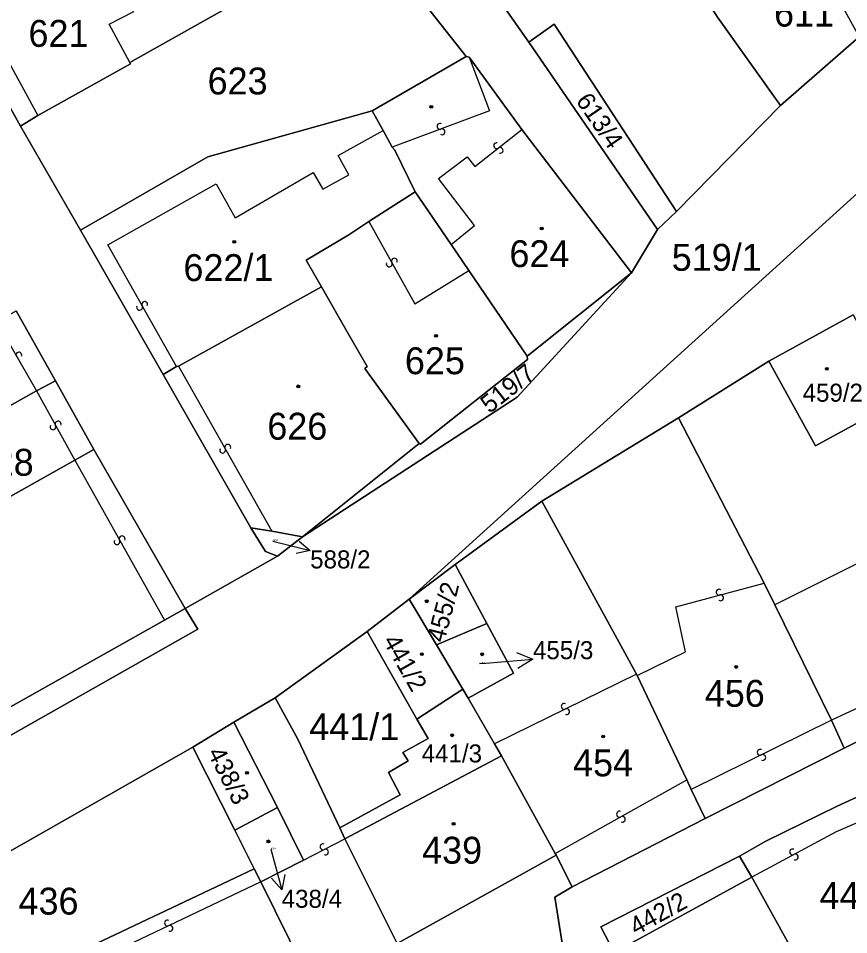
# Model space of a CAD drawing. Extents: x -598233 to -596890, y -1157848 to -1156431.
# Drawn here: x -597383.6 to -597331, y -1157497.1 to -1157439.2 of the extents above; entities that cross this region are included whole.
import ezdxf

# ---------------------------------------------------------------- set-up
doc = ezdxf.new("R2010")
doc.units = 0
for name, color, linetype in [('Level 1', 7, 'Continuous'), ('Level 13', 7, 'Continuous'), ('Level 3', 7, 'Continuous'), ('Level 4', 7, 'Continuous'), ('Level 5', 7, 'Continuous'), ('Level 57', 7, 'Continuous'), ('Level 60', 7, 'Continuous')]:
    doc.layers.add(name, color=color, linetype=linetype)

msp = doc.modelspace()

# ---------------------------------------------------------------- linework, layer by layer
at = {"layer": 'Level 1'}
for points in [[(-597376.5, -1157441.98), (-597366.03, -1157436.07), (-597362.03, -1157433.69), (-597361.89, -1157433.82), (-597361.56, -1157433.56)], [(-597361.56, -1157433.56), (-597355.23, -1157441.59)], [(-597354.11, -1157436.61), (-597351.28, -1157440.68)], [(-597388.35, -1157437.12), (-597383.41, -1157446)], [(-597339.34, -1157439.1), (-597335.35, -1157444.7)], [(-597351.28, -1157440.68), (-597349.67, -1157439.54), (-597341.93, -1157451.4)], [(-597335.35, -1157444.7), (-597330.38, -1157440.35)], [(-597351.28, -1157440.68), (-597343.14, -1157452.53)], [(-597361.17, -1157445.03), (-597355.23, -1157441.59)], [(-597355.23, -1157441.59), (-597355.05, -1157441.63)], [(-597355.05, -1157441.63), (-597351.71, -1157446.21)], [(-597382.33, -1157445.33), (-597376.47, -1157442.05), (-597376.5, -1157441.98)], [(-597379.63, -1157452.57), (-597371.58, -1157447.94), (-597361.17, -1157445.03)], [(-597361.17, -1157445.03), (-597360.49, -1157446.27)], [(-597341.93, -1157451.4), (-597335.35, -1157444.7)], [(-597383.41, -1157446), (-597382.33, -1157445.33)], [(-597383.41, -1157446), (-597379.63, -1157452.57)], [(-597360.49, -1157446.27), (-597359.91, -1157447.33)], [(-597344.79, -1157455.26), (-597351.71, -1157446.21)], [(-597358.47, -1157450.14), (-597359.74, -1157447.51), (-597359.91, -1157447.33)], [(-597358.85, -1157475.91), (-597329.82, -1157449.62)], [(-597361.39, -1157452.03), (-597358.47, -1157450.14)], [(-597356.19, -1157453.47), (-597358.47, -1157450.14)], [(-597341.93, -1157451.4), (-597343.14, -1157452.53)], [(-597364.38, -1157456.16), (-597365.35, -1157454.47), (-597362.66, -1157452.86), (-597361.39, -1157452.03)], [(-597379.63, -1157452.57), (-597374.4, -1157461.7)], [(-597343.14, -1157452.53), (-597344.79, -1157455.26)], [(-597355.07, -1157455.12), (-597356.19, -1157453.47)], [(-597344.79, -1157455.26), (-597352, -1157463.13), (-597365.58, -1157471.97)], [(-597351.38, -1157460.55), (-597355.07, -1157455.12)], [(-597344.79, -1157455.26), (-597351.38, -1157460.55)], [(-597373.42, -1157461.17), (-597364.38, -1157456.16)], [(-597364.38, -1157456.16), (-597362.67, -1157459.14), (-597361.49, -1157461.2), (-597361.64, -1157461.32), (-597358.21, -1157466.07)], [(-597381.21, -1157462.09), (-597383.69, -1157457.67)], [(-597330.77, -1157457.93), (-597336.09, -1157460.85)], [(-597358.21, -1157466.07), (-597358.13, -1157466.11), (-597351.35, -1157460.74), (-597351.38, -1157460.55)], [(-597374.4, -1157461.7), (-597373.56, -1157461.2)], [(-597373.56, -1157461.2), (-597373.42, -1157461.17)], [(-597336.09, -1157460.85), (-597341.81, -1157464.43)], [(-597336.09, -1157460.85), (-597333.15, -1157466.22), (-597327.85, -1157463.33)], [(-597374.4, -1157461.7), (-597368.86, -1157471.4)], [(-597381.21, -1157462.09), (-597382.41, -1157462.74)], [(-597378.79, -1157466.45), (-597381.21, -1157462.09)], [(-597390.52, -1157467.29), (-597382.41, -1157462.74)], [(-597341.81, -1157464.43), (-597350.45, -1157469.7)], [(-597341.81, -1157464.43), (-597336.4, -1157474.89)], [(-597379.99, -1157467.11), (-597378.79, -1157466.45)], [(-597378.79, -1157466.45), (-597373, -1157476.49)], [(-597365.58, -1157471.97), (-597358.21, -1157466.07)], [(-597388.09, -1157471.67), (-597379.99, -1157467.11)], [(-597355.94, -1157473.72), (-597350.45, -1157469.7)], [(-597350.45, -1157469.7), (-597344.47, -1157480.64)], [(-597368.86, -1157471.4), (-597367.93, -1157472.9), (-597367.16, -1157473.19)], [(-597368.86, -1157471.4), (-597367.52, -1157471.61)], [(-597367.52, -1157471.61), (-597365.58, -1157471.97)], [(-597365.58, -1157471.97), (-597367.16, -1157473.19)], [(-597367.16, -1157473.19), (-597373, -1157476.49)], [(-597358.85, -1157475.91), (-597355.94, -1157473.72)], [(-597355.94, -1157473.72), (-597353.93, -1157477.45)], [(-597336.4, -1157474.89), (-597335.72, -1157476.26)], [(-597361.5, -1157477.94), (-597358.85, -1157475.91)], [(-597357.12, -1157478.8), (-597358.85, -1157475.91)], [(-597335.72, -1157476.26), (-597332.13, -1157483.56)], [(-597373, -1157476.49), (-597372.2, -1157477.8), (-597398.69, -1157492.81)], [(-597374.31, -1157477.24), (-597373, -1157476.49)], [(-597399.45, -1157491.38), (-597374.31, -1157477.24)], [(-597353.93, -1157477.45), (-597357.12, -1157478.8)], [(-597353.93, -1157477.45), (-597352.25, -1157480.58), (-597355.11, -1157482.16)], [(-597361.5, -1157477.94), (-597367.32, -1157482.15)], [(-597361.5, -1157477.94), (-597358.35, -1157483.5)], [(-597355.44, -1157481.6), (-597357.12, -1157478.8)], [(-597331.33, -1157485.32), (-597318.93, -1157479.22)], [(-597344.47, -1157480.64), (-597344.42, -1157480.74)], [(-597344.42, -1157480.74), (-597341.29, -1157487.33)], [(-597358.35, -1157483.5), (-597355.44, -1157481.6)], [(-597355.11, -1157482.16), (-597355.44, -1157481.6)], [(-597367.32, -1157482.15), (-597369.92, -1157483.69)], [(-597363.22, -1157490.36), (-597365.88, -1157484.75), (-597367.32, -1157482.15)], [(-597353.45, -1157485.05), (-597355.11, -1157482.16)], [(-597369.92, -1157483.69), (-597372.53, -1157485.26)], [(-597367.16, -1157489.07), (-597369.92, -1157483.69)], [(-597363.22, -1157490.36), (-597359.4, -1157488.28), (-597360.15, -1157486.86), (-597358.91, -1157486.13), (-597359.24, -1157485.61), (-597357.63, -1157484.71), (-597358.35, -1157483.5)], [(-597332.13, -1157483.56), (-597331.33, -1157485.32)], [(-597353.01, -1157485.82), (-597353.45, -1157485.05)], [(-597372.53, -1157485.26), (-597395.1, -1157498.09)], [(-597372.53, -1157485.26), (-597369.86, -1157490.52)], [(-597340.13, -1157489.77), (-597331.33, -1157485.32)], [(-597353.01, -1157485.82), (-597362.9, -1157491.06)], [(-597349.61, -1157491.99), (-597353.01, -1157485.82)], [(-597341.29, -1157487.33), (-597341, -1157487.93)], [(-597341, -1157487.93), (-597340.13, -1157489.77)], [(-597329.02, -1157487.73), (-597331.77, -1157489), (-597336.29, -1157491.2), (-597337.96, -1157492.15)], [(-597369.86, -1157490.52), (-597367.16, -1157489.07)], [(-597367.16, -1157489.07), (-597365.52, -1157492.4)], [(-597348.53, -1157494.09), (-597340.13, -1157489.77)], [(-597362.9, -1157491.06), (-597363.22, -1157490.36)], [(-597369.86, -1157490.52), (-597368.64, -1157492.96)], [(-597359.6, -1157497.68), (-597362.9, -1157491.06)], [(-597349.55, -1157492.1), (-597359.6, -1157497.68)], [(-597349.55, -1157492.1), (-597349.61, -1157491.99)], [(-597348.53, -1157494.09), (-597349.55, -1157492.1)], [(-597365.52, -1157492.4), (-597368.23, -1157493.78)], [(-597337.96, -1157492.15), (-597346.71, -1157496.62), (-597345.88, -1157498.25)], [(-597337.96, -1157492.15), (-597337.18, -1157493.48)], [(-597392.61, -1157504.29), (-597368.64, -1157492.96)], [(-597368.64, -1157492.96), (-597368.23, -1157493.78)], [(-597368.23, -1157493.78), (-597366.4, -1157497.45)], [(-597337.18, -1157493.48), (-597345.88, -1157498.25)], [(-597337.18, -1157493.48), (-597333.59, -1157499.96)], [(-597348.53, -1157494.09), (-597349.62, -1157494.74), (-597348.96, -1157498.98), (-597347.23, -1157502.9)]]:
    msp.add_lwpolyline(points, dxfattribs=at)
at = {"layer": 'Level 13'}
for centre, start, end in [((-597356.894, -1157446.007), 57.63273, 290.22273), ((-597356.767, -1157446.353), 237.84719, 109.94519), ((-597353.313, -1157447.234), 75.60656, 307.70456), ((-597353.087, -1157447.525), 255.3921, 127.9821), ((-597359.778, -1157454.532), 336.56774, 208.66574), ((-597360.101, -1157454.709), 156.35329, 28.94329), ((-597375.569, -1157457.27), 336.54079, 209.13079), ((-597375.892, -1157457.449), 156.75524, 28.85324), ((-597383.52, -1157460.469), 337.44132, 209.53931), ((-597381.038, -1157464.832), 336.34935, 208.44735), ((-597381.361, -1157465.008), 156.1349, 28.7249), ((-597370.631, -1157466.48), 156.63055, 29.22055), ((-597370.309, -1157466.301), 336.84501, 208.943), ((-597377.311, -1157472.269), 156.4381, 29.0281), ((-597376.988, -1157472.091), 336.65255, 208.75055), ((-597339.237, -1157475.462), 52.54078, 284.63878), ((-597339.143, -1157475.818), 232.32632, 104.91632), ((-597349.04, -1157482.684), 63.31353, 295.90353), ((-597348.88, -1157483.016), 243.52799, 115.62598), ((-597336.641, -1157485.585), 63.38645, 295.97645), ((-597336.48, -1157485.916), 243.60091, 115.6989), ((-597345.539, -1157489.498), 66.62575, 298.72375), ((-597345.361, -1157489.821), 246.4113, 119.0013), ((-597364.292, -1157491.565), 64.46023, 296.55822), ((-597364.127, -1157491.894), 244.24577, 116.83577), ((-597334.596, -1157491.887), 65.33091, 297.92091), ((-597334.424, -1157492.213), 245.54537, 117.64337), ((-597374.118, -1157496.384), 62.64841, 295.23841), ((-597373.962, -1157496.717), 242.86287, 114.96087)]:
    msp.add_arc(centre, 0.184, start, end, dxfattribs=at)
at = {"layer": 'Level 3'}
for points in [[(-597376.5, -1157441.98), (-597377.81, -1157439.54), (-597376.26, -1157438.74), (-597376.87, -1157437.62), (-597368.8, -1157433.07), (-597369.59, -1157431.67), (-597364.87, -1157428.9)], [(-597387.12, -1157436.51), (-597382.33, -1157445.33)], [(-597355.05, -1157441.63), (-597353.75, -1157445.03), (-597359.91, -1157447.33)], [(-597373.56, -1157461.2), (-597377.89, -1157453.51), (-597371.04, -1157449.64), (-597369.84, -1157451.79), (-597364.9, -1157448.92), (-597364.29, -1157449.98), (-597362.66, -1157449.07), (-597363.32, -1157447.86), (-597360.49, -1157446.27)], [(-597356.19, -1157453.47), (-597354.71, -1157452.28), (-597356.99, -1157449.3), (-597355.17, -1157447.94), (-597354.68, -1157448.55), (-597351.71, -1157446.21)], [(-597361.39, -1157452.03), (-597358.49, -1157457.22), (-597355.07, -1157455.12)], [(-597384.94, -1157458.37), (-597382.41, -1157462.74)], [(-597373.42, -1157461.17), (-597367.52, -1157471.61)], [(-597382.41, -1157462.74), (-597379.99, -1157467.11)], [(-597379.99, -1157467.11), (-597374.31, -1157477.24)], [(-597323.86, -1157470.33), (-597335.72, -1157476.26)], [(-597344.42, -1157480.74), (-597341.37, -1157479.23), (-597341.97, -1157476.4), (-597336.4, -1157474.89)], [(-597319.75, -1157477.8), (-597332.13, -1157483.56)], [(-597344.47, -1157480.64), (-597353.45, -1157485.05)], [(-597332.13, -1157483.56), (-597341, -1157487.93)], [(-597349.61, -1157491.99), (-597341.29, -1157487.33)], [(-597328.37, -1157489.12), (-597331.84, -1157490.62), (-597337.18, -1157493.48)], [(-597365.52, -1157492.4), (-597362.9, -1157491.06)], [(-597368.23, -1157493.78), (-597379.85, -1157499.32)]]:
    msp.add_lwpolyline(points, dxfattribs=at)
at = {"layer": 'Level 5'}
for centre, radius in [((-597357.44, -1157444.77), 0.09), ((-597357.44, -1157444.77), 0.0521), ((-597350.46, -1157452.47), 0.09), ((-597350.46, -1157452.47), 0.0521), ((-597369.9, -1157453.31), 0.09), ((-597369.9, -1157453.31), 0.0521), ((-597357.14, -1157459.25), 0.09), ((-597357.14, -1157459.25), 0.0521), ((-597332.43, -1157461.34), 0.09), ((-597332.43, -1157461.34), 0.0521), ((-597365.85, -1157462.45), 0.09), ((-597365.85, -1157462.45), 0.0521), ((-597357.73, -1157476.04), 0.09), ((-597357.73, -1157476.04), 0.0521), ((-597358.04, -1157479.38), 0.09), ((-597358.04, -1157479.38), 0.0521), ((-597354.22, -1157479.39), 0.09), ((-597354.22, -1157479.39), 0.0521), ((-597338.16, -1157480.19), 0.09), ((-597338.16, -1157480.19), 0.0521), ((-597356.12, -1157484.51), 0.09), ((-597356.12, -1157484.51), 0.0521), ((-597346.57, -1157484.59), 0.09), ((-597346.57, -1157484.59), 0.0521), ((-597369.09, -1157486.89), 0.09), ((-597369.09, -1157486.89), 0.0521), ((-597356.03, -1157490.11), 0.09), ((-597356.03, -1157490.11), 0.0521), ((-597367.74, -1157491.22), 0.09), ((-597367.74, -1157491.22), 0.0521)]:
    msp.add_circle(centre, radius, dxfattribs=at)
at = {"layer": 'Level 57'}
for p, q in [((-597367.47, -1157472.23), (-597365.1, -1157472.82)), ((-597354, -1157479.948), (-597351.01, -1157479.7)), ((-597354.39, -1157479.98), (-597354, -1157479.948)), ((-597367.58, -1157491.72), (-597366.9, -1157494.28))]:
    msp.add_line(p, q, dxfattribs=at)
for points in [[(-597365.792, -1157472.228), (-597365.1, -1157472.82), (-597365.988, -1157473.018)], [(-597352.048, -1157479.285), (-597351.01, -1157479.7), (-597351.966, -1157480.281)], [(-597366.7, -1157493.313), (-597366.9, -1157494.28), (-597367.553, -1157493.54)]]:
    msp.add_lwpolyline(points, dxfattribs=at)
at = {"layer": 'Level 60'}
for points in [[(-597387.12, -1157436.51), (-597367.26, -1157425.34), (-597364.87, -1157428.9), (-597361.56, -1157433.56), (-597361.89, -1157433.82), (-597362.03, -1157433.69), (-597366.03, -1157436.07), (-597376.5, -1157441.98), (-597376.47, -1157442.05), (-597382.33, -1157445.33), (-597383.41, -1157446), (-597388.35, -1157437.12)], [(-597354.11, -1157436.61), (-597351.17, -1157434.63), (-597339.44, -1157426.66), (-597337.46, -1157428.85), (-597336.03, -1157430.42), (-597338.44, -1157431.99), (-597340.05, -1157433.04), (-597342.28, -1157434.49), (-597341.15, -1157436.26), (-597339.34, -1157439.1), (-597335.35, -1157444.7), (-597341.93, -1157451.4), (-597349.67, -1157439.54), (-597351.28, -1157440.68)], [(-597342.28, -1157434.49), (-597340.05, -1157433.04), (-597338.44, -1157431.99), (-597336.03, -1157430.42), (-597334.94, -1157432.08), (-597330.38, -1157440.35), (-597335.35, -1157444.7), (-597339.34, -1157439.1), (-597341.15, -1157436.26)], [(-597383.41, -1157446), (-597382.33, -1157445.33), (-597376.47, -1157442.05), (-597376.5, -1157441.98), (-597366.03, -1157436.07), (-597362.03, -1157433.69), (-597361.89, -1157433.82), (-597361.56, -1157433.56), (-597355.23, -1157441.59), (-597361.17, -1157445.03), (-597371.58, -1157447.94), (-597379.63, -1157452.57)], [(-597341.93, -1157451.4), (-597343.14, -1157452.53), (-597351.28, -1157440.68), (-597349.67, -1157439.54)], [(-597360.49, -1157446.27), (-597361.17, -1157445.03), (-597355.23, -1157441.59), (-597355.05, -1157441.63), (-597351.71, -1157446.21), (-597344.79, -1157455.26), (-597351.38, -1157460.55), (-597355.07, -1157455.12), (-597356.19, -1157453.47), (-597358.47, -1157450.14), (-597359.74, -1157447.51), (-597359.91, -1157447.33)], [(-597365.35, -1157454.47), (-597364.38, -1157456.16), (-597373.42, -1157461.17), (-597373.56, -1157461.2), (-597374.4, -1157461.7), (-597379.63, -1157452.57), (-597371.58, -1157447.94), (-597361.17, -1157445.03), (-597360.49, -1157446.27), (-597359.91, -1157447.33), (-597359.74, -1157447.51), (-597358.47, -1157450.14), (-597361.39, -1157452.03), (-597362.66, -1157452.86)], [(-597364.38, -1157456.16), (-597365.35, -1157454.47), (-597362.66, -1157452.86), (-597361.39, -1157452.03), (-597358.47, -1157450.14), (-597356.19, -1157453.47), (-597355.07, -1157455.12), (-597351.38, -1157460.55), (-597351.35, -1157460.74), (-597358.13, -1157466.11), (-597358.21, -1157466.07), (-597361.64, -1157461.32), (-597361.49, -1157461.2), (-597362.67, -1157459.14)], [(-597351.38, -1157460.55), (-597344.79, -1157455.26), (-597352, -1157463.13), (-597365.58, -1157471.97), (-597358.21, -1157466.07), (-597358.13, -1157466.11), (-597351.35, -1157460.74)], [(-597364.38, -1157456.16), (-597362.67, -1157459.14), (-597361.49, -1157461.2), (-597361.64, -1157461.32), (-597358.21, -1157466.07), (-597365.58, -1157471.97), (-597367.52, -1157471.61), (-597368.86, -1157471.4), (-597374.4, -1157461.7), (-597373.56, -1157461.2), (-597373.42, -1157461.17)], [(-597381.21, -1157462.09), (-597382.41, -1157462.74), (-597390.52, -1157467.29), (-597392.19, -1157468.23), (-597394.48, -1157469.44), (-597395.74, -1157467.09), (-597396.81, -1157465.08), (-597393.45, -1157463.21), (-597392.23, -1157462.51), (-597384.97, -1157458.39), (-597384.94, -1157458.37), (-597383.69, -1157457.67)], [(-597330.77, -1157457.93), (-597327.85, -1157463.33), (-597333.15, -1157466.22), (-597336.09, -1157460.85)], [(-597327.85, -1157463.33), (-597324.72, -1157468.97), (-597324.18, -1157469.77), (-597323.86, -1157470.33), (-597319.83, -1157477.66), (-597319.75, -1157477.8), (-597318.93, -1157479.22), (-597331.33, -1157485.32), (-597332.13, -1157483.56), (-597335.72, -1157476.26), (-597336.4, -1157474.89), (-597341.81, -1157464.43), (-597336.09, -1157460.85), (-597333.15, -1157466.22)], [(-597381.21, -1157462.09), (-597378.79, -1157466.45), (-597379.99, -1157467.11), (-597388.09, -1157471.67), (-597392.01, -1157473.8), (-597394.48, -1157469.44), (-597392.19, -1157468.23), (-597390.52, -1157467.29), (-597382.41, -1157462.74)], [(-597341.81, -1157464.43), (-597336.4, -1157474.89), (-597335.72, -1157476.26), (-597332.13, -1157483.56), (-597331.33, -1157485.32), (-597340.13, -1157489.77), (-597341, -1157487.93), (-597341.29, -1157487.33), (-597344.42, -1157480.74), (-597344.47, -1157480.64), (-597350.45, -1157469.7)], [(-597378.79, -1157466.45), (-597373, -1157476.49), (-597374.31, -1157477.24), (-597399.45, -1157491.38), (-597405.22, -1157481.31), (-597392.78, -1157474.22), (-597392.01, -1157473.8), (-597388.09, -1157471.67), (-597379.99, -1157467.11)], [(-597341, -1157487.93), (-597340.13, -1157489.77), (-597348.53, -1157494.09), (-597349.55, -1157492.1), (-597349.61, -1157491.99), (-597353.01, -1157485.82), (-597353.45, -1157485.05), (-597355.11, -1157482.16), (-597352.25, -1157480.58), (-597353.93, -1157477.45), (-597355.94, -1157473.72), (-597350.45, -1157469.7), (-597344.47, -1157480.64), (-597344.42, -1157480.74), (-597341.29, -1157487.33)], [(-597365.58, -1157471.97), (-597367.16, -1157473.19), (-597367.93, -1157472.9), (-597368.86, -1157471.4), (-597367.52, -1157471.61)], [(-597358.85, -1157475.91), (-597355.94, -1157473.72), (-597353.93, -1157477.45), (-597357.12, -1157478.8)], [(-597357.12, -1157478.8), (-597355.44, -1157481.6), (-597358.35, -1157483.5), (-597361.5, -1157477.94), (-597358.85, -1157475.91)], [(-597373, -1157476.49), (-597372.2, -1157477.8), (-597398.69, -1157492.81), (-597399.45, -1157491.38), (-597374.31, -1157477.24)], [(-597355.11, -1157482.16), (-597355.44, -1157481.6), (-597357.12, -1157478.8), (-597353.93, -1157477.45), (-597352.25, -1157480.58)], [(-597367.32, -1157482.15), (-597361.5, -1157477.94), (-597358.35, -1157483.5), (-597357.63, -1157484.71), (-597359.24, -1157485.61), (-597358.91, -1157486.13), (-597360.15, -1157486.86), (-597359.4, -1157488.28), (-597363.22, -1157490.36), (-597365.88, -1157484.75)], [(-597355.44, -1157481.6), (-597355.11, -1157482.16), (-597353.45, -1157485.05), (-597353.01, -1157485.82), (-597362.9, -1157491.06), (-597363.22, -1157490.36), (-597359.4, -1157488.28), (-597360.15, -1157486.86), (-597358.91, -1157486.13), (-597359.24, -1157485.61), (-597357.63, -1157484.71), (-597358.35, -1157483.5)], [(-597369.92, -1157483.69), (-597367.32, -1157482.15), (-597365.88, -1157484.75), (-597363.22, -1157490.36), (-597362.9, -1157491.06), (-597359.6, -1157497.68), (-597359.3, -1157498.28), (-597355.61, -1157505.62), (-597355.01, -1157506.82), (-597360.37, -1157509.54), (-597360.99, -1157508.29), (-597362.46, -1157505.35), (-597366.4, -1157497.45), (-597368.23, -1157493.78), (-597365.52, -1157492.4), (-597367.16, -1157489.07)], [(-597372.53, -1157485.26), (-597369.92, -1157483.69), (-597367.16, -1157489.07), (-597369.86, -1157490.52)], [(-597372.53, -1157485.26), (-597369.86, -1157490.52), (-597368.64, -1157492.96), (-597392.61, -1157504.29), (-597395.1, -1157498.09)], [(-597353.01, -1157485.82), (-597349.61, -1157491.99), (-597349.55, -1157492.1), (-597359.6, -1157497.68), (-597362.9, -1157491.06)], [(-597329.02, -1157487.73), (-597328.37, -1157489.12), (-597324.75, -1157496.13), (-597328, -1157497.67), (-597333.52, -1157500.08), (-597333.59, -1157499.96), (-597337.18, -1157493.48), (-597337.96, -1157492.15), (-597336.29, -1157491.2), (-597331.77, -1157489)], [(-597367.16, -1157489.07), (-597365.52, -1157492.4), (-597368.23, -1157493.78), (-597368.64, -1157492.96), (-597369.86, -1157490.52)], [(-597355.01, -1157506.82), (-597355.61, -1157505.62), (-597359.3, -1157498.28), (-597359.6, -1157497.68), (-597349.55, -1157492.1), (-597348.53, -1157494.09), (-597349.62, -1157494.74), (-597348.96, -1157498.98), (-597347.23, -1157502.9)], [(-597337.96, -1157492.15), (-597337.18, -1157493.48), (-597345.88, -1157498.25), (-597346.71, -1157496.62)], [(-597360.99, -1157508.29), (-597360.37, -1157509.54), (-597374.66, -1157516.44), (-597374.79, -1157516.18), (-597383, -1157500.84), (-597383.27, -1157500.98), (-597383.18, -1157501.15), (-597386.63, -1157503.02), (-597386.71, -1157502.86), (-597387.09, -1157503.04), (-597387.26, -1157502.71), (-597392.12, -1157505.28), (-597392.61, -1157504.29), (-597368.64, -1157492.96), (-597368.23, -1157493.78), (-597366.4, -1157497.45), (-597362.46, -1157505.35)], [(-597337.18, -1157493.48), (-597333.59, -1157499.96), (-597343, -1157504.42), (-597345.88, -1157498.25)]]:
    msp.add_lwpolyline(points, close=True, dxfattribs=at)
for points in [[(-597354.11, -1157436.61), (-597351.28, -1157440.68), (-597343.14, -1157452.53), (-597344.79, -1157455.26), (-597351.71, -1157446.21), (-597355.05, -1157441.63), (-597355.23, -1157441.59), (-597361.56, -1157433.56)], [(-597388.35, -1157437.12), (-597383.41, -1157446), (-597379.63, -1157452.57), (-597374.4, -1157461.7), (-597368.86, -1157471.4), (-597367.93, -1157472.9), (-597367.16, -1157473.19), (-597373, -1157476.49), (-597378.79, -1157466.45), (-597381.21, -1157462.09), (-597383.69, -1157457.67)], [(-597398.69, -1157492.81), (-597372.2, -1157477.8), (-597373, -1157476.49), (-597367.16, -1157473.19), (-597365.58, -1157471.97), (-597352, -1157463.13), (-597344.79, -1157455.26), (-597343.14, -1157452.53), (-597341.93, -1157451.4), (-597335.35, -1157444.7), (-597330.38, -1157440.35)], [(-597329.82, -1157449.62), (-597358.85, -1157475.91), (-597361.5, -1157477.94), (-597367.32, -1157482.15), (-597369.92, -1157483.69), (-597372.53, -1157485.26), (-597395.1, -1157498.09)], [(-597330.77, -1157457.93), (-597336.09, -1157460.85), (-597341.81, -1157464.43), (-597350.45, -1157469.7), (-597355.94, -1157473.72), (-597358.85, -1157475.91), (-597329.82, -1157449.62)], [(-597348.96, -1157498.98), (-597349.62, -1157494.74), (-597348.53, -1157494.09), (-597340.13, -1157489.77), (-597331.33, -1157485.32), (-597318.93, -1157479.22)], [(-597329.02, -1157487.73), (-597331.77, -1157489), (-597336.29, -1157491.2), (-597337.96, -1157492.15), (-597346.71, -1157496.62), (-597345.88, -1157498.25)]]:
    msp.add_lwpolyline(points, dxfattribs=at)

# ---------------------------------------------------------------- texts
at = {"layer": 'Level 4'}
for s, height, p in [('611', 1.7, (-597335.77, -1157439.7)), ('621', 1.7, (-597382.912, -1157440.98)), ('623', 1.7, (-597371.586, -1157443.99)), ('624', 1.7, (-597352.499, -1157454.91)), ('519/1', 1.7, (-597342.236, -1157455.14)), ('622/1', 1.7, (-597373.112, -1157455.79)), ('625', 1.7, (-597359.111, -1157461.68)), ('459/2', 1.14, (-597333.96, -1157463.42)), ('626', 1.7, (-597367.809, -1157465.82)), ('628', 1.7, (-597386.377, -1157468.1)), ('588/2', 0.1, (-597367.47, -1157472.23)), ('455/3', 0.1, (-597354.39, -1157479.98)), ('456', 1.7, (-597340.146, -1157482.71)), ('441/1', 1.7, (-597365.155, -1157484.82)), ('441/3', 1.14, (-597358.046, -1157486.23)), ('454', 1.7, (-597348.476, -1157487.11)), ('439', 1.7, (-597358.021, -1157492.63)), ('438/4', 0.1, (-597367.58, -1157491.72)), ('443', 1.7, (-597332.891, -1157495.49)), ('436', 1.7, (-597383.541, -1157495.85))]:
    msp.add_text(s, height=height, dxfattribs=at).set_placement(p)
for s, rotation, p in [('613/4', 304.48593, (-597348.337, -1157444.392)), ('519/7', 38.3805, (-597353.756, -1157464.199)), ('455/2', 75.43062, (-597356.623, -1157478.7)), ('441/2', 299.53359, (-597360.526, -1157478.543)), ('438/3', 296.91252, (-597371.618, -1157485.614)), ('442/2', 28.73493, (-597344.497, -1157497.193))]:
    msp.add_text(s, height=1.14, rotation=rotation, dxfattribs=at).set_placement(p)
at = {"layer": 'Level 57'}
for s, p in [('588/2', (-597365.1, -1157473.96)), ('455/3', (-597351.01, -1157479.7)), ('438/4', (-597366.9, -1157495.42))]:
    msp.add_text(s, height=1.14, dxfattribs=at).set_placement(p)

doc.saveas('drawing.dxf')
